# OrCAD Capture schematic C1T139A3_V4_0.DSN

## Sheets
1 000_NOTE: title: Telink-Semi; rev: V4.0; note: C1T139A3
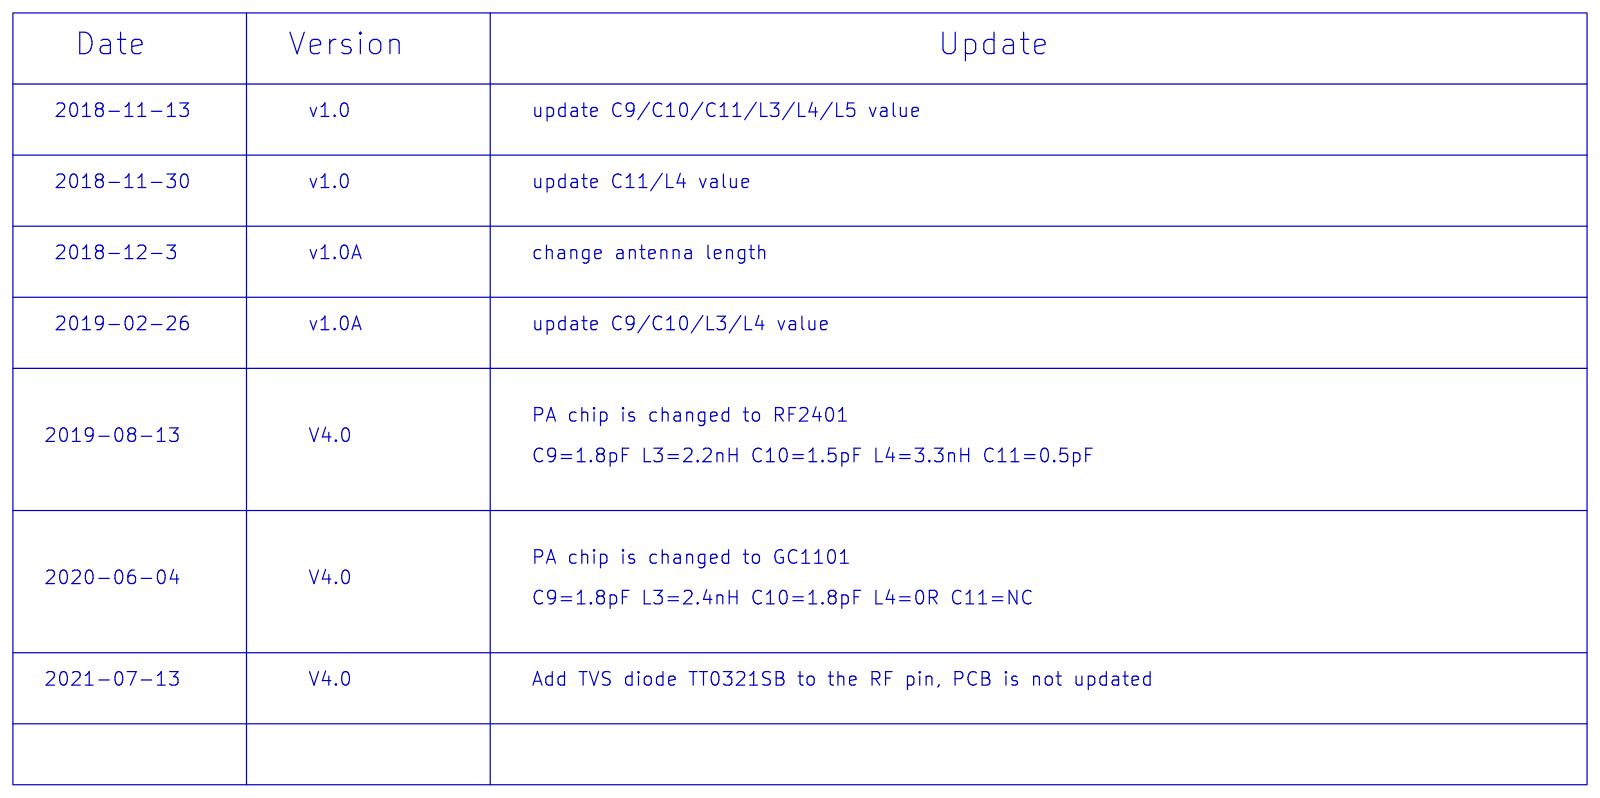
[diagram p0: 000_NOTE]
2 main: size A4
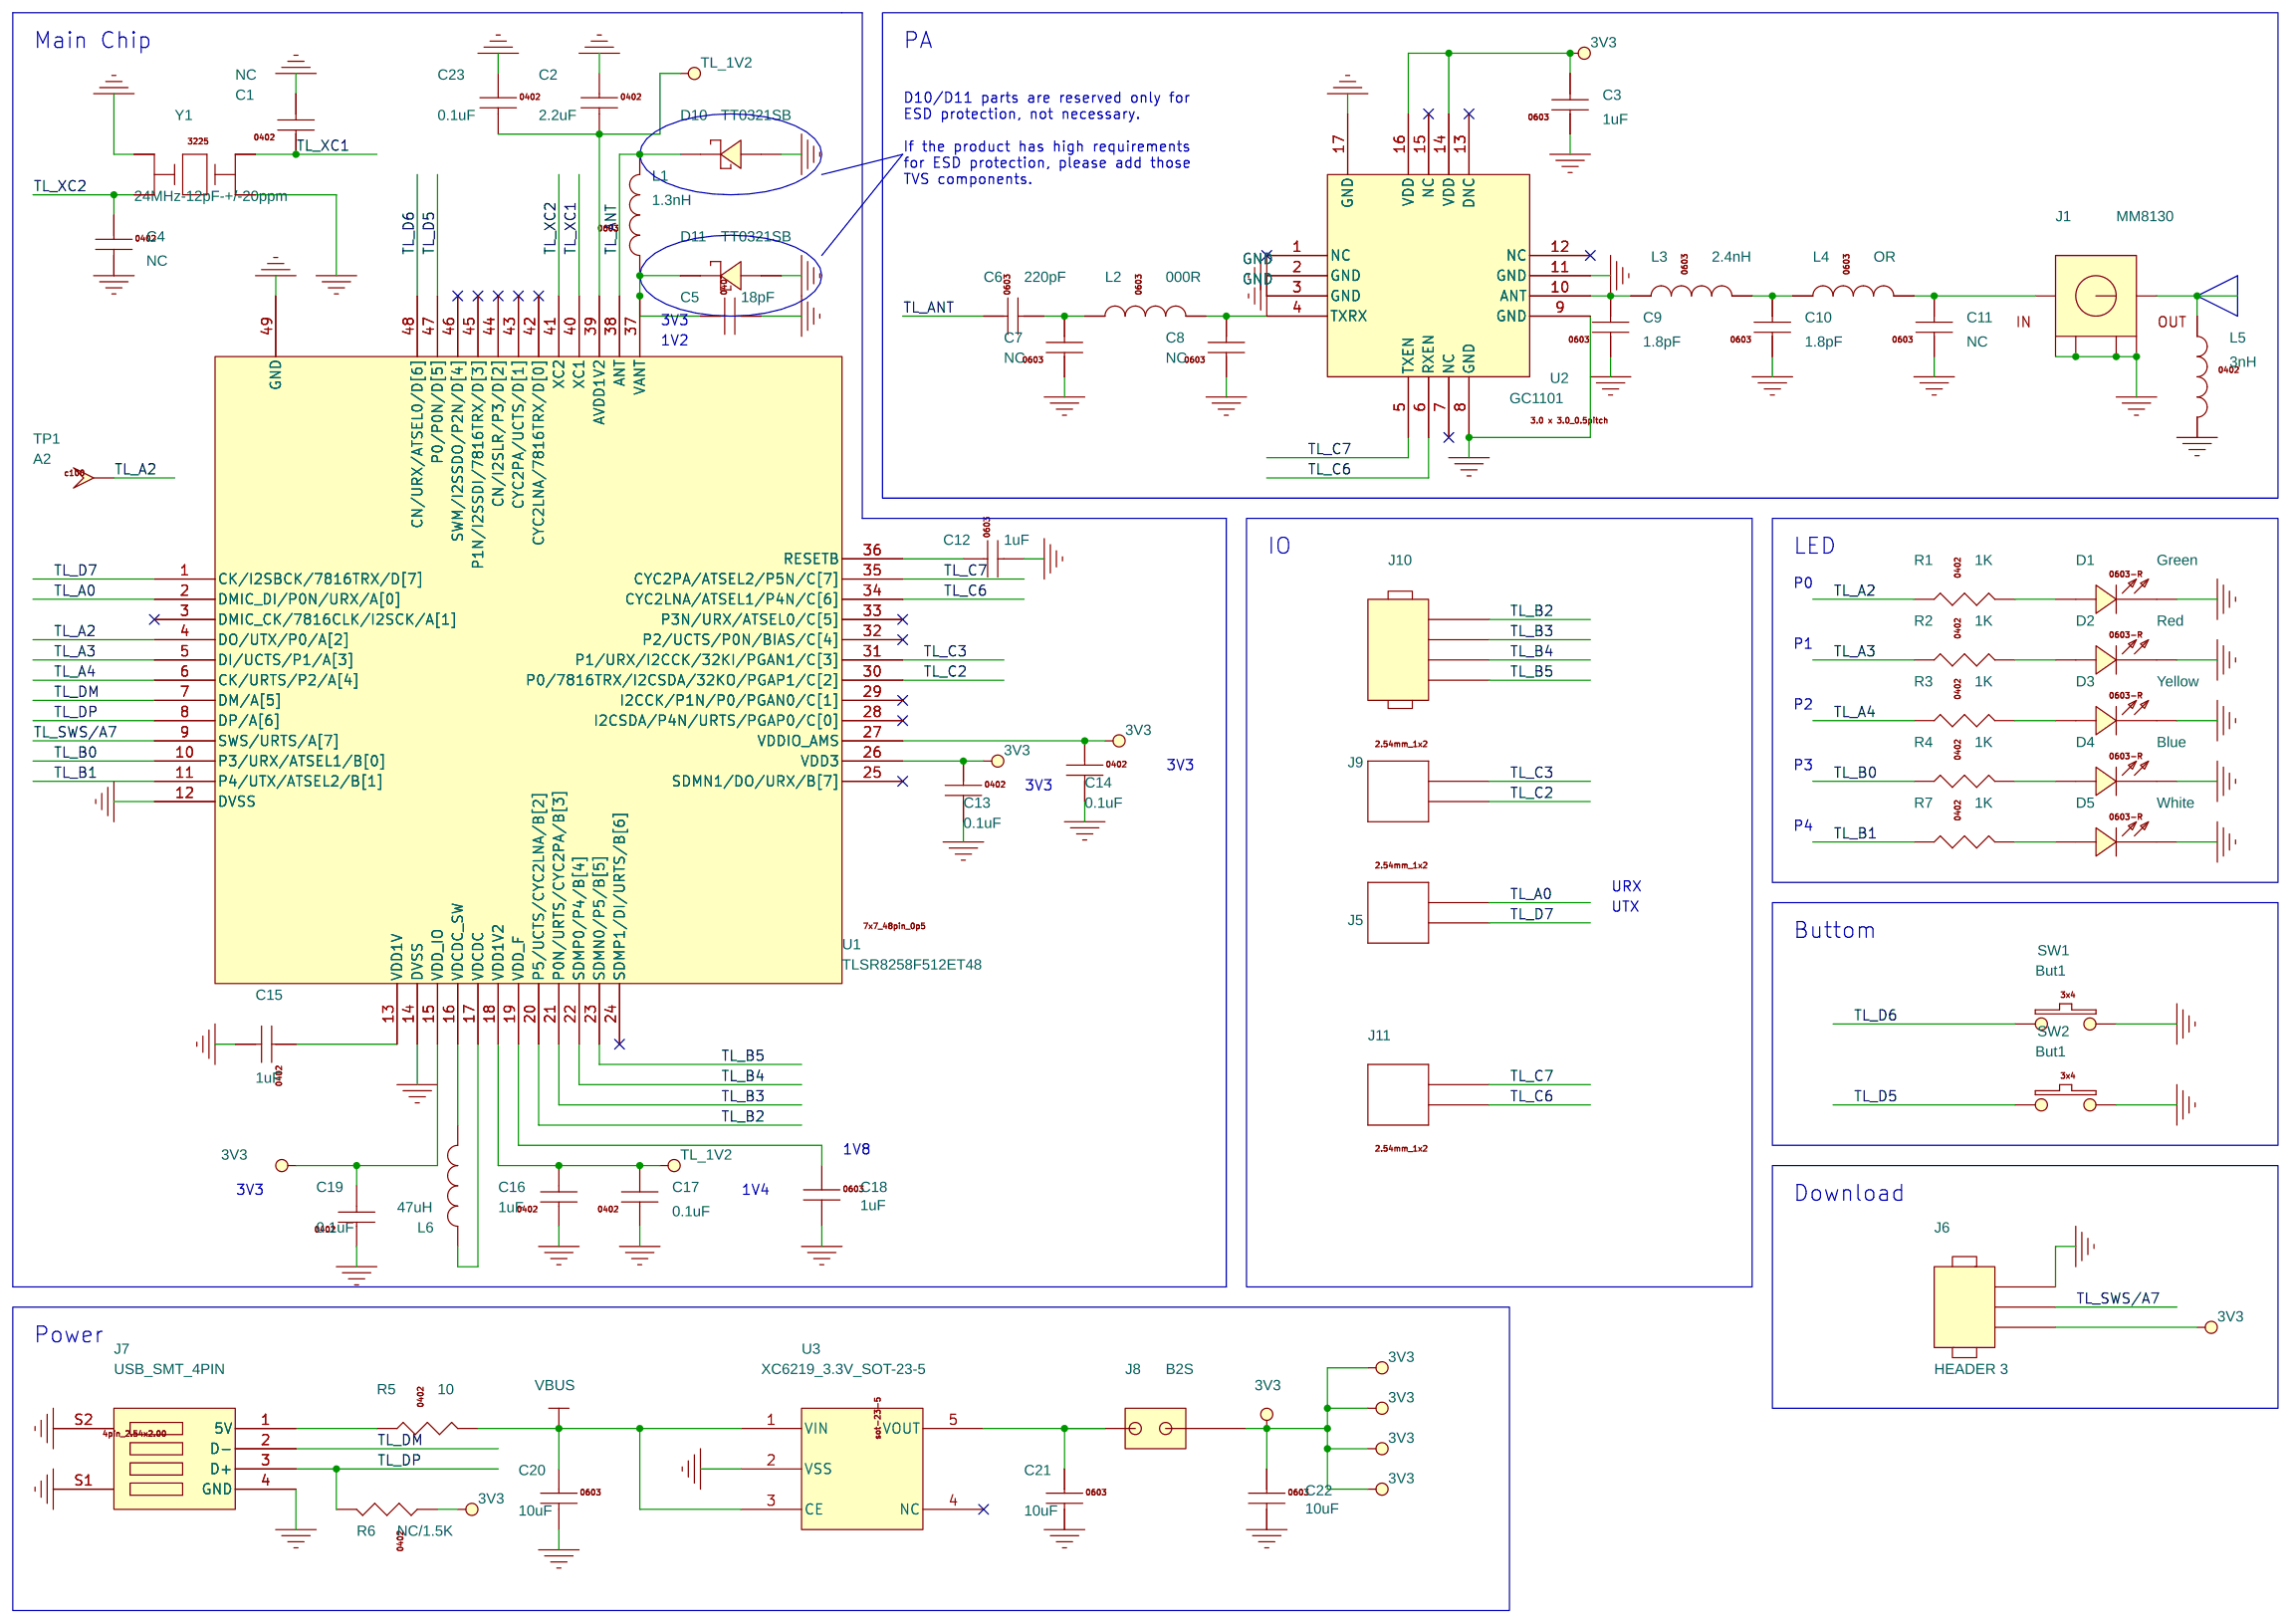
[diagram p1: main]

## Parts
C1  NC  [0402]
C2  2.2uF  [0402]
C3  1uF  [0402]
C4  NC  [0402]
C5  18pF  [0402]
C6  220pF  [0402]
C7  NC  [0402]
C8  NC  [0402]
C9  1.8pF  [0402]
C10  1.8pF  [0402]
C11  NC  [0402]
C12  1uF  [0402]
C13  0.1uF  [0402]
C14  0.1uF  [0402]
C15  1uF  [0402]
C16  1uF  [0402]
C17  0.1uF  [0402]
C18  1uF  [0402]
C19  0.1uF  [0402]
C20  10uF  [0603C]
C21  10uF  [0603C]
C22  10uF  [0603C]
C23  0.1uF  [0402]
D1  Green  [0603-LED]
D2  Red  [0603-LED]
D3  Yellow  [0603-LED]
D4  Blue  [0603-LED]
D5  White  [0603-LED]
D10  TT0321SB  [SOD-123]
D11  TT0321SB  [SOD-123]
J1  MM8130  [MM8130-2600]
J5  CON_2.54mm_1x2  [hdr254f-1x2x850]
J6  HEADER 3  [hdr254m-1x3]
J7  USB_SMT_4PIN  [usb-m-4]
J8  B2S  [HDR254F-1X2X850]
J9  CON_2.54mm_1x2  [hdr254f-1x2x850]
J10  HEADER 4  [hdr254f-1x4x850]
J11  CON_2.54mm_1x2  [hdr254f-1x2x850]
L1  1.3nH  [0402]
L2  000R  [0402]
L3  2.4nH  [0402]
L4  OR  [0402]
L5  3nH  [0402]
L6  47uH  [0805L]
R1  1K  [0402]
R2  1K  [0402]
R3  1K  [0402]
R4  1K  [0402]
R5  10  [0402]
R6  NC/1.5K  [0402]
R7  1K  [0402]
SW1  But1  [butsmd2px4_00y3_00_nh]
SW2  But1  [butsmd2px4_00y3_00_nh]
TP1  A2  [TP100]
U1  TLSR8258F512ET48  [qfn_7x7_48pin_0p5_4p20x4p20]
U2  GC1101  [qfn_3x3_16pin_0p5_1p70x1p70]
U3  XC6219_3.3V_SOT-23-5  [sot-23-5]
Y1  24MHz-12pF-+/-20ppm  [osccc200x250x080]

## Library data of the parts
C1 C4 = C1005_NC
C2 C13 C14 C23 = C1005X5R1C104K
C3 C6-C11 = C1608_NC
C5 = C1005C0G1H100D
C12 = C1608X5R1C105M
C15-C17 C19 = C1005X5R1C105K
C18 C20-C22 = C1608X5R0J106M
D1-D5 = 0603D_Red
D10 D11 = DIODE_SCHOTTKY_0
J1 = MM8130
J5 J9 J11 = CON_2.54mm_1x2
J6 = HEADER_3
J7 = USB_SMT_1
J8 = B2S_0
J10 = HEADER_4
L1-L4 = MLK1608_000R
L5 = MLK1005S1N5ST
L6 = IND_0
R1-R4 R7 = RS0402K332JT
R5 R6 = RS0402K100JT
SW1 SW2 = SW2PIN_3x4
TP1 = TestPad100
U1 = TLSR8258F512ET48
U2 = RFX2401C_11
U3 = XC6219_1.3V_SOT-23-5
Y1 = OSC_25x32_4pin

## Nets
3V3: C3.2 C13.1 C14.1 C19.2 C22.1 J6.3 J8.2 R6.1 U1.15(VDD_IO) U1.26(VDD3) U1.27(VDDIO_AMS) U2.14(VDD) U2.16(VDD)
GND: C1.2 C2.1 C3.1 C4.2 C5.2 C7.1 C8.1 C9.1 C10.1 C11.1 C12.2 C13.2 C14.2 C15.2 C16.1 C17.1 C18.2 C19.1 C20.2 C21.2 C22.2 C23.1 D1.C(CATHODE) D2.C(CATHODE) D3.C(CATHODE) D4.C(CATHODE) D5.C(CATHODE) D10.A(ANODE) D11.A(ANODE) J1.3 J1.4 J1.5 J1.6 J6.1 J7.4(GND) J7.S1 J7.S2 L5.2 SW1.2 SW2.2 U1.12(DVSS) U1.14(DVSS) U1.49(GND) U2.2(GND) U2.3(GND) U2.8(GND) U2.9(GND) U2.11(GND) U2.17(GND) U3.2(VSS) Y1.2 Y1.4
VBUS: C20.1 R5.2 U3.1(VIN) U3.3(CE)
TL_1V2: C2.2 C16.2 C17.2 C23.2 U1.18(VDD1V2) U1.39(AVDD1V2)
TL_A0: J5.1 U1.2(DMIC_DI/P0N/URX/A[0])
TL_A2: R1.1 TP1.1(TP) U1.4(DO/UTX/P0/A[2])
TL_A3: R2.1 U1.5(DI/UCTS/P1/A[3])
TL_A4: R3.1 U1.6(CK/URTS/P2/A[4])
TL_ANT: C6.1 D10.C(CATHODE) L1.2 U1.38(ANT)
TL_B0: R4.1 U1.10(P3/URX/ATSEL1/B[0])
TL_B1: R7.1 U1.11(P4/UTX/ATSEL2/B[1])
TL_B2: J10.1 U1.20(P5/UCTS/CYC2LNA/B[2])
TL_B3: J10.2 U1.21(P0N/URTS/CYC2PA/B[3])
TL_B4: J10.3 U1.22(SDMP0/P4/B[4])
TL_B5: J10.4 U1.23(SDMN0/P5/B[5])
TL_C2: J9.2 U1.30(P0/7816TRX/I2CSDA/32KO/PGAP1/C[2])
TL_C3: J9.1 U1.31(P1/URX/I2CCK/32KI/PGAN1/C[3])
TL_C6: J11.1 U1.34(CYC2LNA/ATSEL1/P4N/C[6]) U2.6(RXEN)
TL_C7: J11.2 U1.35(CYC2PA/ATSEL2/P5N/C[7]) U2.5(TXEN)
TL_D5: SW2.1 U1.47(P0/P0N/D[5])
TL_D6: SW1.1 U1.48(CN/URX/ATSEL0/D[6])
TL_D7: J5.2 U1.1(CK/I2SBCK/7816TRX/D[7])
TL_DM: J7.2(D-) U1.7(DM/A[5])
TL_DP: J7.3(D+) R6.2 U1.8(DP/A[6])
TL_SWS/A7: J6.2 U1.9(SWS/URTS/A[7])
TL_XC1: C1.1 U1.40(XC1) Y1.3
TL_XC2: C4.1 U1.41(XC2) Y1.1
N14798367: C18.1 U1.19(VDD_F)
N14798471: L6.1 U1.17(VDCDC)
N14798499: L6.2 U1.16(VDCDC_SW)
N14798557: C15.1 U1.13(VDD1V)
N14798729: C12.1 U1.36(RESETB)
N14798863: C5.1 D11.C(CATHODE) L1.1 U1.37(VANT)
N14803016: C6.2 C7.2 L2.1
N14803042: C8.2 L2.2 U2.4(TXRX)
N14803152: C10.2 L3.2 L4.1
N14803180: C9.2 L3.1 U2.10(ANT)
N14803220: C11.2 J1.1 L4.2
N14803264: J1.2 L5.1
N14807404: D1.A(ANODE) R1.2
N14807456: D3.A(ANODE) R3.2
N14807480: D4.A(ANODE) R4.2
N14807598: D2.A(ANODE) R2.2
N14823075: C21.1 J8.1 U3.5(VOUT)
N14823079: J7.1(5V) R5.1
N14826545: D5.A(ANODE) R7.2

Not connected (* = marked no-connect by the designer): U1 3(DMIC_CK/7816CLK/I2SCK/A[1])* 24(SDMP1/DI/URTS/B[6])* 25(SDMN1/DO/URX/B[7])* 28(I2CSDA/P4N/URTS/PGAP0/C[0])* 29(I2CCK/P1N/P0/PGAN0/C[1])* 32(P2/UCTS/P0N/BIAS/C[4])* 33(P3N/URX/ATSEL0/C[5])* 42(CYC2LNA/7816TRX/D[0])* 43(CYC2PA/UCTS/D[1])* 44(CN/I2SLR/P3/D[2])* 45(P1N/I2SSDI/7816TRX/D[3])* 46(SWM/I2SSDO/P2N/D[4])*; U2 1(NC)* 7(NC)* 12(NC)* 13(DNC)* 15(NC)*; U3 4(NC)*

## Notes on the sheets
sheet 1
- Date
- Version
- Update
- 2018-11-13
- v1.0
- update C9/C10/C11/L3/L4/L5 value
- 2018-11-30
- v1.0
- update C11/L4 value
- 2018-12-3
- v1.0A
- change antenna length
- 2019-02-26
- v1.0A
- update C9/C10/L3/L4 value
- PA chip is changed to RF2401
- 2019-08-13
- V4.0
- C9=1.8pF L3=2.2nH C10=1.5pF L4=3.3nH C11=0.5pF
- PA chip is changed to GC1101
- 2020-06-04
- V4.0
- C9=1.8pF L3=2.4nH C10=1.8pF L4=0R C11=NC
- 2021-07-13
- V4.0
- Add TVS diode TT0321SB to the RF pin, PCB is not updated
sheet 2
- Main Chip
- PA
- D10/D11 parts are reserved only for
  ESD protection, not necessary.
  If the product has high requirements
  for ESD protection, please add those
  TVS components.
- 3V3
- 1V2
- IO
- LED
- P0
- P1
- P2
- 3V3
- P3
- 3V3
- P4
- URX
- UTX
- Buttom
- 1V8
- 3V3
- 1V4
- Download
- Power
